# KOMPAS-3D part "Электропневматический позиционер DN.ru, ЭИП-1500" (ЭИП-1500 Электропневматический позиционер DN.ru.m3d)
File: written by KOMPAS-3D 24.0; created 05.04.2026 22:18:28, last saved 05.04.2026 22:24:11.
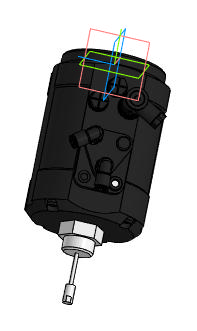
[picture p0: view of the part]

Document properties: Автор: R2D2; Полное имя файла: E:\Работа\Зайцев\Аксессуары для пневмоприводов\Электропневматические позиционеры DN.ru\ЭИП Электропневматический позиционер DN.ru\ЭИП-1500 Электропневматический позиционер DN.ru\5-25\ЭИП-1500 Электропневматический позиционер DN.ru.m3d

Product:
- Body: Тело 2  | qty 1
    Масса: 8.188644
- Part/product: Электропневматический позиционер DN.ru  | designation ЭИП-1500
    Масса: 0.14
    Раздел спецификации: Прочие изделия
    Примечание: D900-02741

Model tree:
1. Операция без истории:1

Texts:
  ЭИП-1500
